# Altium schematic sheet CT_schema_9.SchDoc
size 403 x 220 mm
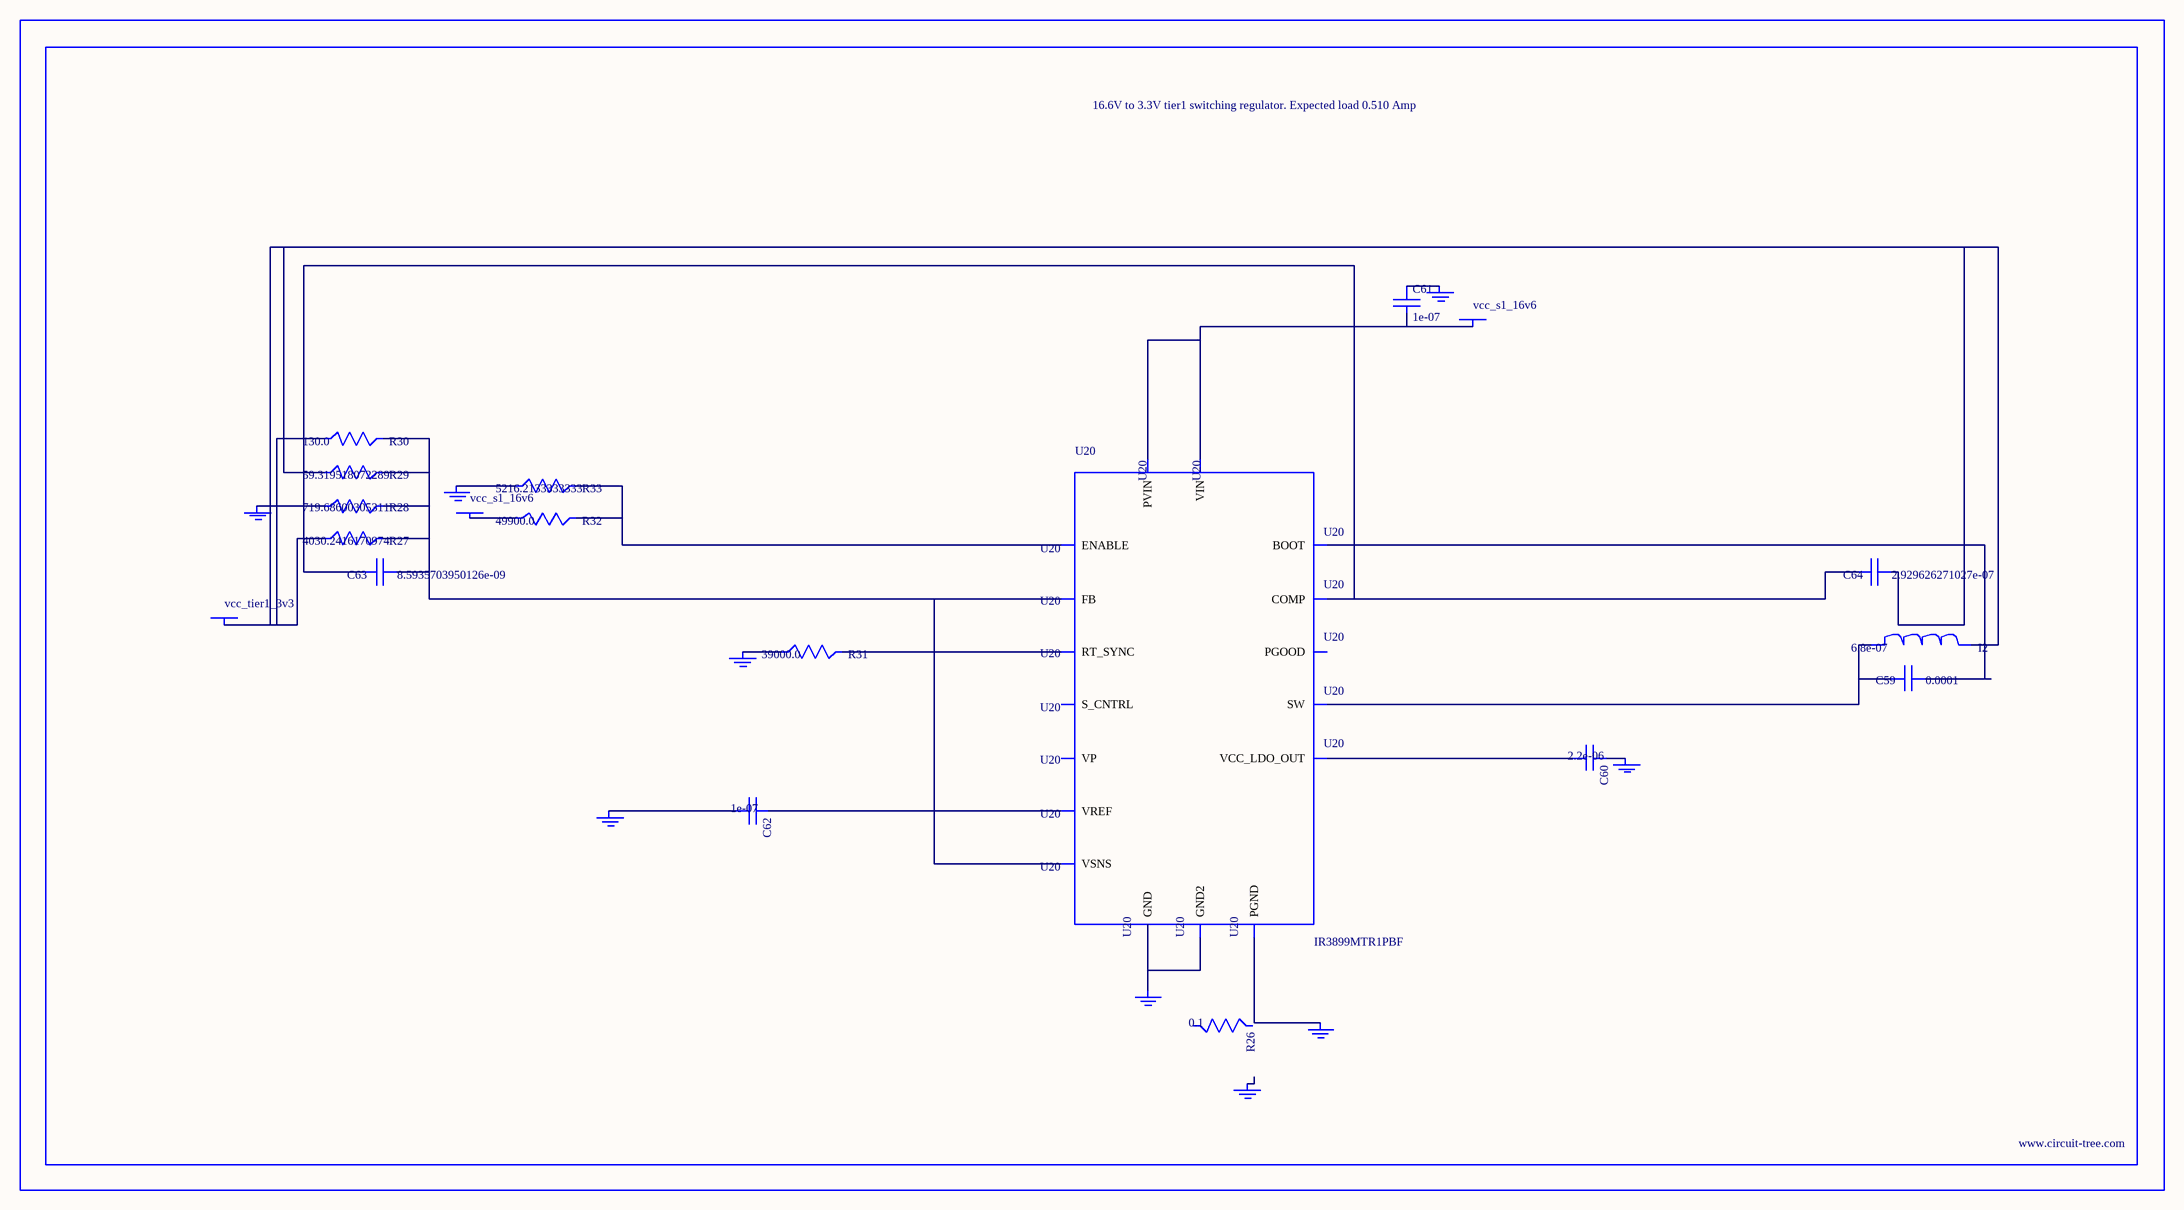
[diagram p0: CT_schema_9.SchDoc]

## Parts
BORDER8  (no value)
C59  0.0001  [C1210]
C60  2.2e-06  [C0603]
C61  1e-07  [C0402]
C62  1e-07  [C0402]
C63  8.5935703950126e-09  [R0603]
C64  2.929626271027e-07  [R0603]
GND_INSTANCE_8_0  (no value)
GND_INSTANCE_8_1  (no value)
GND_INSTANCE_8_2  (no value)
GND_INSTANCE_8_3  (no value)
GND_INSTANCE_8_4  (no value)
GND_INSTANCE_8_5  (no value)
GND_INSTANCE_8_6  (no value)
GND_INSTANCE_8_7  (no value)
GND_INSTANCE_8_8  (no value)
I2  6.8e-07  [IND25X25CZ]
POWER_INSTANCE_8_0  vcc_s1_16v6
POWER_INSTANCE_8_1  vcc_s1_16v6
POWER_INSTANCE_8_2  vcc_tier1_3v3
R26  0.1  [R0603]
R27  4030.2416170974  [R0603]
R28  719.68600305311  [R0603]
R29  59.319518072289  [R0603]
R30  130.0  [R0603]
R31  39000.0  [R0603]
R32  49900.0  [R0603]
R33  5216.2133333333  [R0603]
U20  IR3899MTR1PBF  [IR3899MTR1PBF]

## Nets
NetC59_1: C59.1 U20.14(BOOT)
NetC59_2: C59.2 I2.1 U20.12(SW)
NetC60_1: C60.1 GND_INSTANCE_8_4.0(GND)
NetC60_2: C60.2 U20.10(VCC_LDO_OUT)
NetC61_1: C61.1 GND_INSTANCE_8_3.0(GND)
NetC61_2: C61.2 POWER_INSTANCE_8_0.0(PWR) U20.9(VIN) U20.13(PVIN)
NetC62_1: C62.1 U20.2(VREF)
NetC62_2: C62.2 GND_INSTANCE_8_1.0(GND)
NetC63_1: C63.1 R27.2 R28.2 R29.2 R30.2 U20.1(FB) U20.8(VSNS)
NetC63_2: C63.2 C64.2 U20.3(COMP)
NetC64_1: C64.1 I2.2 POWER_INSTANCE_8_2.0(PWR) R27.1 R29.1 R30.1
NetGND_INSTANCE_8_0_0: GND_INSTANCE_8_0.0(GND) R28.1
NetGND_INSTANCE_8_2_0: GND_INSTANCE_8_2.0(GND) R31.1
NetGND_INSTANCE_8_6_0: GND_INSTANCE_8_6.0(GND) U20.11(PGND)
NetGND_INSTANCE_8_7_0: GND_INSTANCE_8_7.0(GND) R33.1
NetGND_INSTANCE_8_8_0: GND_INSTANCE_8_8.0(GND) U20.4(GND) U20.17(GND2)
NetPOWER_INSTANCE_8_1_0: POWER_INSTANCE_8_1.0(PWR) R32.1
NetR31_2: R31.2 U20.5(RT_SYNC)
NetR32_2: R32.2 R33.2 U20.15(ENABLE)

Not connected (* = marked no-connect by the designer): GND_INSTANCE_8_5 0(GND); R26 1 2; U20 6(S_CNTRL) 7(PGOOD) 16(VP)

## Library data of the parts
BORDER8 = BORDER_PAGE8
C59 = GRM32ER61A107ME20L
C60 = C0603C225K8RACTU
C61 C62 = C0402C104K3RACTU
C63 = C63
C64 = C64
GND_INSTANCE_8_0-GND_INSTANCE_8_8 = GND
I2 = IHLP2525CZERR68M01
POWER_INSTANCE_8_0-POWER_INSTANCE_8_2 = PWR
R26 = ERJ-3RSFR10V
R27 = R27
R28 = R28
R29 = R29
R30 = RC0603JR-07130RL
R31 = RC0603JR-0739KL
R32 = RC0603FR-0749K9
R33 = R33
